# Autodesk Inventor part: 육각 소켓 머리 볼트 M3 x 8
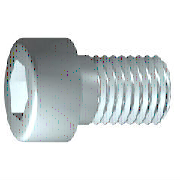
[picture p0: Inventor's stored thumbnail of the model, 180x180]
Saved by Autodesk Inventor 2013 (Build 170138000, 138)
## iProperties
Created: 2012-02
Part Number: 육각 소켓 머리 볼트 M3 x 8
Material: 강철, 연강
Description: 6각 소켓 머리 캡 나사
Document SubType Name: Modeling
Standard: ISO 4762
Designer: mdu-01
Standard Revision: Fourth edition 2004-03-01
Standards Organization: ISO
Language: ko-KR
Size Designation: M3 x 8
Categories: <MemberInstance><Categories><Category DisplayName="조임쇠" InternalName="e4da775c-781d-43d5-af7c-5136215cf5a6" Mnemonic="FSTN"><Category DisplayName="볼트" InternalN
Density: 7.75 g/cm^3
IsCustomPart: 1
Author: mdu-01
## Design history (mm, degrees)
sketch "스케치1"
  geometry: L1 (-0.867, 0)-(8, 0); L2 (8, 0)-(8, 1.5); L3 (8, 1.5)-(1.25, 1.5); L4 (1.25, 1.5)-(0.943, 1.5); L5 (0.943, 1.5)-(0, 1.5); L6 (0, 1.5)-(0, 2.75); L7 (0, 2.75)-(-3, 2.75); L8 (-3, 2.75)-(-3, 1.443); L9 (-3, 1.443)-(-1.7, 1.443); L10 (-1.7, 1.443)-(-0.867, 0); L11 (-5.2, 0)-(10.2, 0) reference; L12 (0, -0.55)-(0, 3.3) reference; L13 (1.25, 1.5)-(0, 1.5)
  constraints: 22 end point, 6 parallel, 2 collinear, 2 perpendicular, 1 horizontal, 1 point on line
  dimensions: "d1" = 6.75 distance from line of L3.end L2 (= GEL); "d2" = 0.30683 distance of L4.end L3.end (computed from GAL); "d3" = 3 distance between parallel lines of L8 L6 (= KOH); "d4" = 1.3 distance of L8.end L9.end (= INTI); "d5" = 60 deg angle of L10 L1; "d6" = 3 diameter of L3 L1 (= GD); "d7" = 3 diameter of L5 L1 (= BDM); "d8" = 2.88675 diameter of L9 L1 (= 1.1547 x SW); "d9" = 5.5 diameter of L7 L1 (= KOD); "d26" = 8 distance between parallel lines of L12 L2 (= NLG)
revolve "본체" sketch "스케치1" stored, may be unused: angle "d10" = 90 deg
sketch "스케치2"
  geometry: L1 (0, -3.85)-(0, 3.85) reference; L2 (-3.85, 0)-(3.85, 0) reference; L3 (1.443, 0)-(0.722, -1.25); L4 (0.722, -1.25)-(-0.722, -1.25); L5 (-0.722, -1.25)-(-1.443, 0); L6 (-1.443, 0)-(-0.722, 1.25); L7 (-0.722, 1.25)-(0.722, 1.25); L8 (0.722, 1.25)-(1.443, 0); 2 further points
  constraints: 12 end point, 1 coincident, 1 horizontal alignment, 1 point on line, 12 other
extrude "슬롯" join sketch "스케치2" stored distance "d11" = 10; taper "d12" = 0 deg
workplane "Work Plane1"
fillet "Fillet2" dims "d30" = 0.1 (= R)
body "Solid1"
fillet "모깎기1" dims "d17" = 0.3 (= RR)
feature "스레드" dims "d13" = 6.75 (= GEL), "d14" = 0
chamfer "모따기1" distance "d15" = 0.30673 (= -0.5 x SPD + 0.5 x GD); stored, may be unused: second distance "d16" = 0.30673 (= GUL), angle "d27" = 45 deg
other parameters: "GD" = 3 [user parameter; used in 2 equation terms], "NLG" = 8 [user parameter; used in 1 equation term], "GEL" = 6.75 [user parameter; used in 2 equation terms], "KOD" = 5.5 [user parameter; used in 1 equation term], "KOH" = 3 [user parameter; used in 1 equation term], "INTI" = 1.3 [user parameter; used in 1 equation term], "GAL" = 0.30673 (= 0.61345 x PTC) [user parameter; used in 1 equation term], "GUL" = 0.30673 (= 0.61345 x PTC) [user parameter; used in 1 equation term], "BDM" = 3 (= NND) [user parameter; used in 1 equation term], "SW" = 2.5 [user parameter; used in 2 equation terms], "RR" = 0.3 [user parameter; used in 1 equation term], "SPD" = 2.38655 (= NND - 1.2269 x PTC) [user parameter; used in 1 equation term], "d19" = 0, "d28" = 0, "d29" = 0, "R" = 0.1 [user parameter; used in 1 equation term], "TOA" = 30 deg [user parameter], "GD1" = 2.38655 (= THREADDIA - 1.2269 x PTC) [user parameter], "THREADDIA" = 3 [user parameter; used in 1 equation term], "FAWI" = 45 deg [user parameter], "PTC" = 0.5 [user parameter; used in 5 equation terms], "NND" = 3 [user parameter; used in 2 equation terms], "E0" = 2.8875 (= 1.155 x SW) [user parameter]
